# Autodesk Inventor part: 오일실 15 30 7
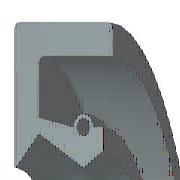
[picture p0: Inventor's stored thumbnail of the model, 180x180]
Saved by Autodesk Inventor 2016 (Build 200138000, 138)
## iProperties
IsCustomPart: 1
Created: 2012-02
Part Number: 오일실 15 30 7
Material: 고무
Description: 오일-실
Document SubType Name: Modeling
Standard: KS B 2804
Designer: mduedu
Standards Organization: KS
Language: ko-KR
Size Designation: D - 15 30 7
Categories: <MemberInstance><Categories><Category DisplayName="샤프트 부품" InternalName="7f7aeb1f-a693-4053-b835-cee3144e0d98" Mnemonic="SHFT"><Category DisplayName="실링" Intern
Density: 0.93 g/cm^3
Appearance: 고무 - 검은색 - 버전 1.1
Author: mduedu
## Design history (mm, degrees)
revolve "본체" stored, may be unused: angle "d17" = 90 deg
revolve "스프링1" stored, may be unused: angle "d18" = 90 deg
body "Solid1"
sketch "스케치1"
  geometry: L1 (0, 15)-(7, 15); L2 (7, 13.25)-(1.75, 13.25); L3 (1.75, 9.25)-(4.9, 7.5); L4 (4.9, 7.5)-(0, 7.5); L5 (0, 0)-(9.586, 0) reference; L6 (4.9, 7.5)-(6.3, 8.375); L7 (0, 18)-(0, -3) reference; L8 (-1.941, 0)-(11.507, 0) reference; L9 (4.2, 9.6)-(1.75, 10.09); L10 (1.75, 10.09)-(1.75, 13.25); L11 (0, 15)-(0, 7.588); L12 (4.9, 7.5)-(0, 7.5); L13 (1.75, 9.25)-(0.152, 7.528); L14 (7, 15)-(7, 13.25); L15 (5.6, 9.6)-(6.3, 9.6); L16 (6.3, 9.6)-(6.3, 8.375); C1 r 0.455 at (4.9, 9.6); A1 r 0.7 centre (4.9, 9.6) between (5.6, 9.6) and (4.2, 9.6); A2 r 0.088 centre (0.088, 7.588) between (0, 7.588) and (0.152, 7.528); 1 further point
  constraints: 28 end point, 5 horizontal alignment, 5 point on line, 4 point on circle, 4 vertical alignment, 3 centre point, 3 tangent, 2 collinear, 2 horizontal, 2 perpendicular, 1 coincident, 1 parallel
  dimensions: "d0" = 30 diameter of L1 L5 (= SD2); "d1" = 1.75 distance of L1.end L2.start (= SD); "d2" = 0.91 diameter of C1 (= SPDI); "d3" = 1.4 diameter of A1 (= SPDA); "d4" = 15 diameter of L3.end L5 (= NND); "d5" = 18.5 diameter of L3.start L5 (= TKDM); "d7" = 20.18 diameter of L9.end L5 (= TKDM + 0.24 x SWDT); "d8" = 1.75 distance between parallel lines of L11 L10 (= SD); "d9" = 4.9 distance from line of L11 C1.centre (= SPDST); "d10" = 19.2 diameter of C1.centre L5 (= HLDM); "d11" = 0.0875 radius of A2 (= 0.25 x LAB); "d12" = 6.3 distance between parallel lines of L11 L16 (= SDI); "d13" = 16.75 diameter of L6.end L5 (= ABDM); "d14" = 7 distance from line of L11 L1.end (= SWDT)
fillet "모깎기1" dims "d6" = 0.3 (= RR)
other parameters: "SD2" = 30 [user parameter; used in 1 equation term], "SWDT" = 7 [user parameter; used in 2 equation terms], "RR" = 0.3 [user parameter; used in 1 equation term], "SD" = 1.75 [user parameter; used in 2 equation terms], "NND" = 15 [user parameter; used in 1 equation term], "SPDA" = 1.4 [user parameter; used in 1 equation term], "SPDI" = 0.91 [user parameter; used in 1 equation term], "TKDM" = 18.5 [user parameter; used in 2 equation terms], "HLDM" = 19.2 [user parameter; used in 1 equation term], "ABDM" = 16.75 [user parameter; used in 1 equation term], "SDI" = 6.3 [user parameter; used in 1 equation term], "SPDST" = 4.9 [user parameter; used in 1 equation term], "LAB" = 0.35 [user parameter; used in 1 equation term], "d15" = 0, "d16" = 0, "d19" = 0
